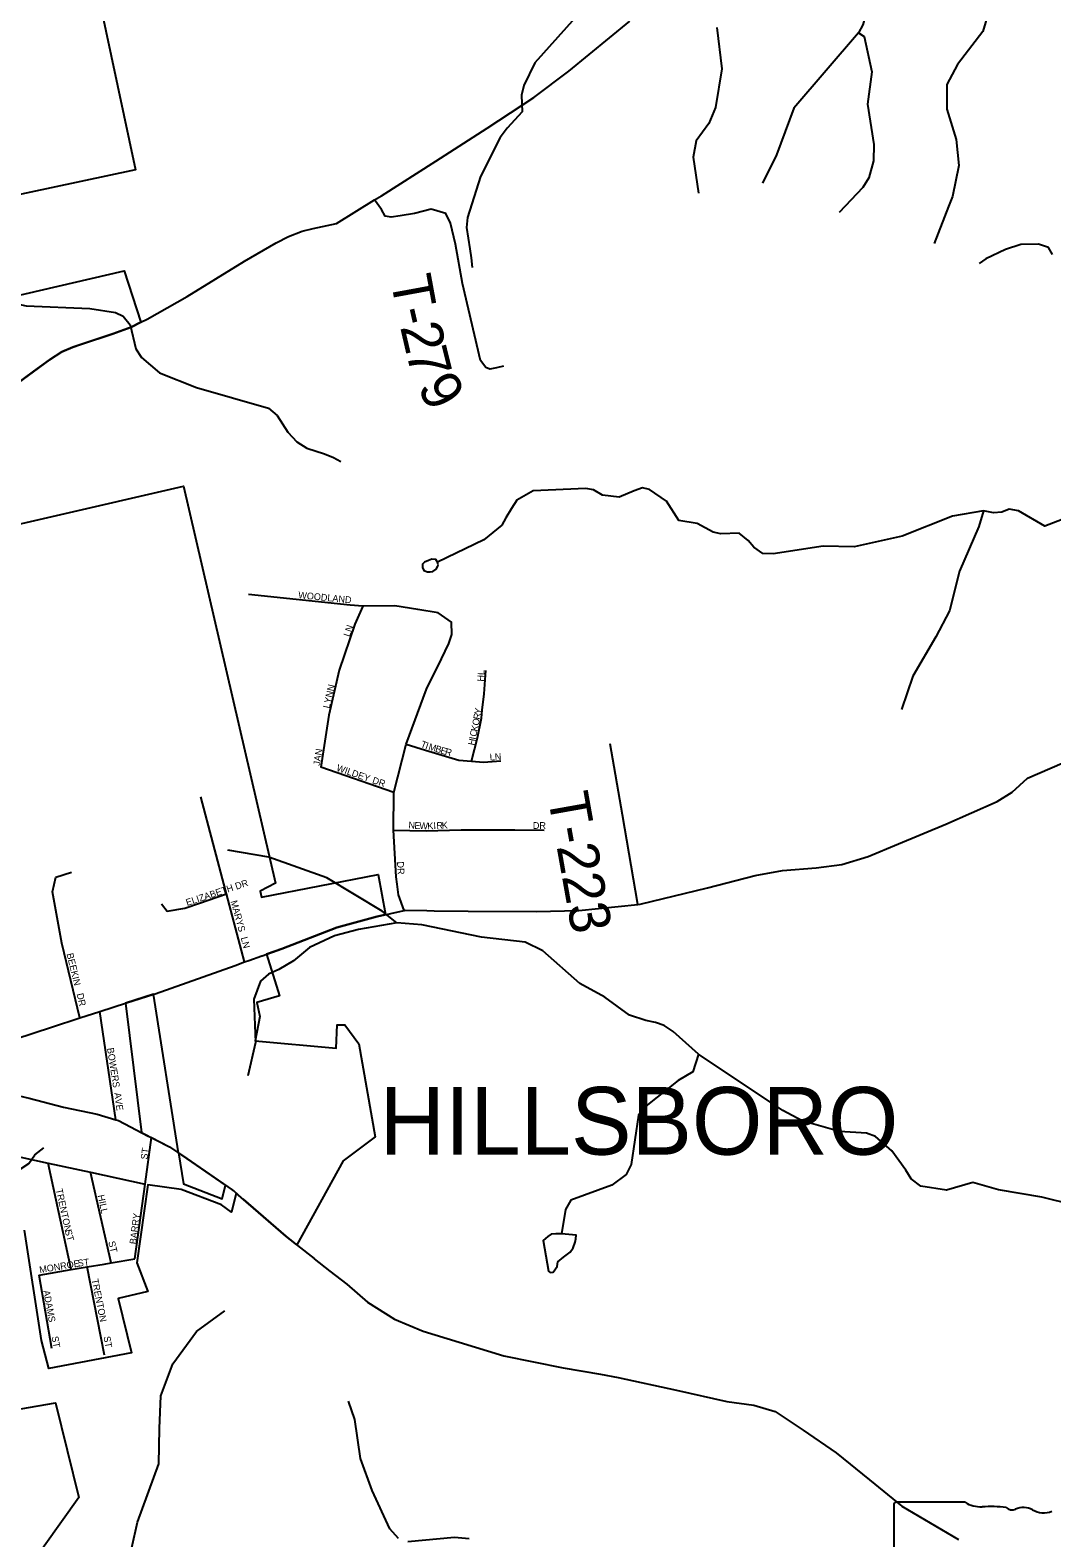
# Model space of a CAD drawing. Extents: x 1525783 to 1900577, y 218250 to 627376.
# Drawn here: x 1656538 to 1664074, y 435875 to 446999 of the extents above; entities that cross this region are included whole.
import ezdxf

# ---------------------------------------------------------------- set-up
doc = ezdxf.new("R2010")
doc.units = 0
for name, color, linetype in [('GM_X_City_Street', 7, 'Continuous'), ('GM_X_City_Street_Text', 7, 'Continuous'), ('GM_X_Corporation', 7, 'Continuous'), ('GM_X_Corporation_Text', 7, 'Continuous'), ('GM_X_Minor_Lake', 7, 'Continuous'), ('GM_X_Minor_River', 7, 'Continuous'), ('GM_X_State_Route', 7, 'Continuous'), ('GM_X_State_Shield', 7, 'Continuous'), ('GM_X_Township_Road', 7, 'Continuous'), ('GM_X_Township_Road_Text', 7, 'Continuous'), ('GM_X_Township_Subdivision', 7, 'Continuous'), ('GM_X_Township_Subdivision_Text', 7, 'Continuous'), ('GM_X_US_Route', 7, 'Continuous')]:
    doc.layers.add(name, color=color, linetype=linetype)

msp = doc.modelspace()

# ---------------------------------------------------------------- linework, layer by layer
at = {"layer": 'GM_X_City_Street'}
for points in [[(1657980, 440653), (1657980, 440653), (1657798, 441342)], [(1656905, 439711), (1656773, 440263), (1656704, 440641), (1656727, 440750), (1656842, 440787)], [(1658120, 440124), (1657987, 440627), (1657980, 440653)], [(1657508, 440554), (1657548, 440499), (1657678, 440520), (1657788, 440558), (1657788, 440558)], [(1657788, 440558), (1657987, 440627)], [(1657170, 438960), (1657051, 439758)], [(1655247, 438934), (1655840, 438817), (1656187, 438745), (1656671, 438640), (1656983, 438572), (1657386, 438484)], [(1657310, 437934), (1657386, 438484), (1657433, 438828)], [(1656840, 437855), (1656671, 438640)], [(1657136, 437904), (1656983, 438572)], [(1656604, 437814), (1656840, 437855), (1656884, 437863), (1656958, 437875), (1657085, 437895), (1657136, 437904), (1657310, 437934)], [(1657087, 437223), (1656958, 437875)], [(1656698, 437271), (1656604, 437814)]]:
    msp.add_lwpolyline(points, dxfattribs=at)
at = {"layer": 'GM_X_Corporation'}
for points in [[(1656785, 448461), (1657315, 445968), (1655515, 445585)], [(1655662, 444859), (1657231, 445224), (1657355, 444844), (1657283, 444808), (1657148, 444760), (1656853, 444660), (1656773, 444626), (1656680, 444567), (1656365, 444336)], [(1655730, 443186), (1657669, 443634), (1658347, 440706), (1658234, 440646), (1658245, 440602), (1659105, 440769), (1659159, 440474), (1659097, 440460), (1658801, 440378), (1658395, 440222), (1658282, 440182), (1658377, 439875), (1658210, 439824), (1658231, 439722), (1658199, 439541), (1658796, 439489), (1658802, 439660), (1658860, 439660), (1658963, 439519), (1659084, 438834), (1658848, 438656), (1658505, 438037), (1658424, 438102), (1658058, 438419), (1658023, 438277), (1657949, 438331), (1657652, 438445), (1657405, 438480), (1657326, 437905), (1657405, 437693), (1657187, 437642), (1657285, 437241), (1656675, 437125), (1656622, 437332), (1656496, 438146)], [(1655588, 436674), (1656726, 436872), (1656897, 436173), (1656268, 435291)]]:
    msp.add_lwpolyline(points, dxfattribs=at)
msp.add_lwpolyline([(1657241, 439819), (1657360, 438865), (1657565, 438759), (1657633, 438715), (1657669, 438487), (1657954, 438377), (1657979, 438477), (1657693, 438675), (1657633, 438715), (1657448, 439886)], close=True, dxfattribs=at)
at = {"layer": 'GM_X_Minor_Lake'}
for points in [[(1659543, 443075), (1659531, 443094), (1659501, 443096), (1659477, 443086), (1659447, 443073), (1659432, 443059), (1659432, 443035), (1659443, 443013), (1659469, 443002), (1659489, 443002), (1659509, 443006), (1659532, 443023), (1659546, 443045), (1659548, 443055)], [(1659548, 443055), (1659543, 443075)], [(1660456, 438118), (1660416, 438119), (1660382, 438116), (1660356, 438098), (1660321, 438069), (1660361, 437843), (1660373, 437833), (1660395, 437835), (1660426, 437878), (1660431, 437912), (1660473, 437946), (1660520, 437983), (1660543, 438015), (1660557, 438057), (1660564, 438082)], [(1660564, 438082), (1660565, 438108), (1660456, 438118)]]:
    msp.add_lwpolyline(points, dxfattribs=at)
at = {"layer": 'GM_X_Minor_River'}
for points in [[(1664100, 448598), (1663841, 448718), (1663657, 448717), (1663494, 448660), (1663379, 448524), (1663290, 448330), (1663239, 448275), (1663117, 448205), (1663045, 448186), (1662982, 448125), (1662940, 448052), (1662878, 447790), (1662756, 447467), (1662746, 447393), (1662716, 447169), (1662680, 447039), (1662647, 446980), (1662172, 446424), (1662044, 446079), (1661940, 445870)], [(1664504, 448468), (1664573, 448417), (1664488, 448266), (1664353, 448126), (1664306, 447938), (1664231, 447811), (1664121, 447685), (1663985, 447579), (1663732, 447448), (1663662, 447323), (1663566, 446990), (1663379, 446745), (1663299, 446599), (1663299, 446417), (1663369, 446193), (1663388, 446000), (1663340, 445772), (1663312, 445699), (1663205, 445426)], [(1661319, 447837), (1661316, 447907), (1661251, 447844), (1661081, 447524), (1661048, 447468), (1660917, 447338), (1660650, 447174), (1660599, 447137), (1660260, 446759), (1660179, 446590), (1660162, 446520), (1660167, 446396), (1660057, 446276), (1660004, 446208), (1659859, 445920), (1659763, 445617), (1659756, 445543), (1659781, 445386), (1659792, 445319), (1659798, 445249)], [(1661602, 447019), (1661639, 446714), (1661592, 446430), (1661545, 446310), (1661451, 446184), (1661429, 446062), (1661468, 445796)], [(1662647, 446980), (1662690, 446953), (1662746, 446693), (1662713, 446453), (1662762, 446155), (1662758, 446035), (1662725, 445911), (1662680, 445838), (1662505, 445654)], [(1664079, 445345), (1664048, 445397), (1663976, 445421), (1663846, 445417), (1663731, 445381), (1663588, 445311), (1663537, 445278)], [(1655107, 445225), (1655112, 445201), (1655372, 445026), (1655521, 444997), (1655977, 445080), (1656508, 444966), (1656978, 444946), (1657167, 444915), (1657225, 444888), (1657276, 444825), (1657317, 444648), (1657360, 444583), (1657492, 444472), (1657766, 444363), (1658296, 444210), (1658361, 444156), (1658439, 444033), (1658506, 443963), (1658579, 443916), (1658708, 443874), (1658776, 443846), (1658829, 443816)], [(1664151, 443390), (1664022, 443340), (1663828, 443452), (1663758, 443465), (1663706, 443444), (1663644, 443437), (1663570, 443454), (1663341, 443414), (1662970, 443266), (1662837, 443236), (1662616, 443186), (1662386, 443193), (1662018, 443136), (1661942, 443137), (1661875, 443184), (1661834, 443235), (1661767, 443288), (1661633, 443282), (1661577, 443295), (1661458, 443360), (1661322, 443382), (1661231, 443524), (1661106, 443610), (1661054, 443623), (1660992, 443600), (1660883, 443554), (1660759, 443568), (1660692, 443607), (1660636, 443618), (1660249, 443601), (1660128, 443531), (1660088, 443469), (1660047, 443400), (1660016, 443348), (1659884, 443240), (1659543, 443075)], [(1663570, 443454), (1663536, 443336), (1663392, 443008), (1663320, 442714), (1663217, 442524), (1663049, 442232), (1662965, 441986)], [(1659242, 440413), (1659134, 440499), (1658726, 440745), (1658298, 440898), (1657995, 440948)], [(1664228, 438331), (1663999, 438389), (1663680, 438443), (1663490, 438496), (1663297, 438441), (1663108, 438470), (1663036, 438524), (1662998, 438587), (1662894, 438731), (1662772, 438837), (1662708, 438860), (1662508, 438872), (1662233, 438951), (1662090, 439027), (1661467, 439443), (1661280, 439610), (1661215, 439656), (1661151, 439677), (1661079, 439692), (1660958, 439732), (1660778, 439864), (1660592, 439965), (1660320, 440206), (1660189, 440269), (1659867, 440308), (1659426, 440398), (1659242, 440413), (1658961, 440364), (1658782, 440317), (1658598, 440232), (1658480, 440133), (1658373, 440069), (1658296, 440034), (1658237, 439983), (1658187, 439849), (1658201, 439530), (1658143, 439283)], [(1661467, 439443), (1661427, 439313), (1661318, 439249), (1661078, 439060), (1661025, 438993), (1660972, 438629), (1660933, 438555), (1660829, 438477), (1660525, 438366), (1660486, 438298), (1660456, 438118)], [(1656059, 435729), (1655940, 435903), (1655888, 436155), (1655841, 436224), (1655697, 436419), (1655627, 436550), (1655592, 436731), (1655577, 437119), (1655580, 437301), (1655548, 437486), (1655416, 437835), (1655419, 437885), (1655489, 438022), (1655537, 438090), (1655642, 438174), (1655797, 438212), (1655993, 438301), (1656349, 438519), (1656529, 438638), (1656573, 438702), (1656640, 438753)], [(1657156, 434742), (1657228, 434845), (1657242, 435085), (1657336, 435410), (1657328, 435525), (1657295, 435658), (1657287, 435804), (1657329, 435990), (1657487, 436420), (1657491, 436681), (1657502, 436923), (1657590, 437158), (1657764, 437398), (1657975, 437549)], [(1659255, 435871), (1659192, 435942), (1659061, 436225), (1658975, 436461), (1658932, 436747), (1658886, 436884)], [(1659777, 435868), (1659669, 435878), (1659324, 435846)]]:
    msp.add_lwpolyline(points, dxfattribs=at)
at = {"layer": 'GM_X_State_Route'}
for points in [[(1657355, 444844), (1657355, 444844), (1657401, 444868), (1657697, 445034), (1658120, 445295), (1658352, 445430), (1658444, 445478), (1658544, 445517), (1658626, 445535), (1658798, 445573), (1659079, 445747), (1659130, 445778), (1659530, 446032), (1659908, 446276), (1660252, 446502), (1660512, 446696), (1660960, 447066)], [(1656909, 444679), (1657148, 444760), (1657283, 444808), (1657355, 444844)], [(1656114, 444163), (1656365, 444336), (1656565, 444483), (1656680, 444567), (1656773, 444626), (1656853, 444660), (1656909, 444679)], [(1655688, 439317), (1655926, 439261), (1656265, 439181), (1656532, 439118), (1656784, 439052), (1657032, 439001), (1657170, 438960), (1657190, 438954), (1657408, 438840)], [(1657408, 438840), (1657410, 438840), (1657433, 438828), (1657565, 438759), (1657693, 438675), (1657724, 438654), (1657725, 438653)], [(1657725, 438653), (1658028, 438444), (1658029, 438443)], [(1658029, 438443), (1658037, 438438), (1658108, 438375), (1658109, 438375)], [(1658109, 438375), (1658424, 438102), (1658510, 438033)], [(1658510, 438033), (1658633, 437935), (1658634, 437934)], [(1658634, 437934), (1658748, 437843), (1658874, 437747), (1659027, 437614), (1659225, 437489), (1659438, 437400), (1659702, 437318), (1660033, 437219), (1660470, 437130), (1660744, 437082)], [(1660744, 437082), (1660874, 437059), (1661305, 436964), (1661677, 436882), (1661876, 436854), (1662034, 436807), (1662239, 436670), (1662484, 436502), (1662730, 436302), (1662968, 436108), (1663385, 435862)]]:
    msp.add_lwpolyline(points, dxfattribs=at)
at = {"layer": 'GM_X_State_Shield'}
for p, q in [((1662908, 436120), (1662908, 435063)), ((1663435, 436138), (1662925, 436138))]:
    msp.add_line(p, q, dxfattribs=at)
for centre, major_axis, start_param, end_param in [((1662928, 436122), (20.2, 0), 1.712693, 3.28349), ((1663556, 436260), (196, 0), 4.042523, 4.731795), ((1663621, 435544), (702, 0), 1.404758, 1.657858), ((1663780, 436127), (56.4, 0), 3.836095, 5.185415), ((1663863, 436005), (117, 0), 0.950623, 2.079405), ((1664015, 436173), (141, 0), 4.081561, 5.145723)]:
    msp.add_ellipse(centre, major_axis=major_axis, ratio=0.8, start_param=start_param, end_param=end_param, dxfattribs=at)
at = {"layer": 'GM_X_Township_Road'}
for points in [[(1660029, 444520), (1659979, 444507), (1659928, 444498), (1659898, 444510), (1659859, 444561), (1659727, 445129), (1659676, 445421), (1659638, 445576), (1659603, 445646), (1659497, 445678), (1659374, 445646), (1659268, 445629), (1659201, 445620), (1659157, 445627), (1659130, 445675), (1659079, 445747)], [(1661019, 440548), (1660907, 441210), (1660815, 441733)]]:
    msp.add_lwpolyline(points, dxfattribs=at)
at = {"layer": 'GM_X_Township_Subdivision'}
for points in [[(1659397, 442725), (1659227, 442752), (1658992, 442749), (1658899, 442757), (1658148, 442836)], [(1658992, 442749), (1658934, 442616), (1658818, 442276), (1658741, 441944), (1658681, 441562)], [(1659572, 442362), (1659626, 442473), (1659649, 442541), (1659647, 442631), (1659547, 442701), (1659397, 442725), (1659397, 442725)], [(1659245, 440699), (1659238, 440752), (1659217, 441096), (1659221, 441374), (1659312, 441732), (1659462, 442136), (1659572, 442362)], [(1659794, 441606), (1659838, 441778), (1659867, 441923), (1659873, 441982), (1659888, 442103), (1659900, 442274)], [(1659312, 441732), (1659453, 441687), (1659701, 441613), (1659794, 441606), (1659883, 441598), (1660010, 441609)], [(1659221, 441374), (1658681, 441562)], [(1659217, 441096), (1659460, 441091), (1659717, 441099), (1659869, 441098), (1660114, 441098), (1660330, 441096)], [(1659297, 440504), (1659254, 440620), (1659245, 440699)]]:
    msp.add_lwpolyline(points, dxfattribs=at)
at = {"layer": 'GM_X_US_Route'}
for points in [[(1659517, 440502), (1659770, 440498), (1660271, 440497), (1660584, 440505), (1661019, 440548), (1661037, 440550), (1661534, 440672), (1661885, 440762), (1662088, 440798), (1662336, 440818), (1662526, 440843), (1662720, 440903), (1662942, 440995), (1663291, 441141), (1663671, 441307), (1663780, 441376), (1663894, 441481), (1664151, 441592)], [(1658248, 440170), (1658250, 440170), (1658395, 440222), (1658801, 440378), (1659097, 440460), (1659099, 440460)], [(1659099, 440460), (1659297, 440504), (1659304, 440506), (1659463, 440503), (1659517, 440502)], [(1657450, 439887), (1657460, 439890), (1658050, 440099), (1658120, 440124), (1658151, 440135), (1658248, 440170)], [(1657249, 439822), (1657450, 439887), (1657450, 439887)], [(1656695, 439643), (1656905, 439711), (1657051, 439758), (1657249, 439822), (1657249, 439822)], [(1655688, 439317), (1656433, 439558), (1656695, 439643), (1656695, 439643)]]:
    msp.add_lwpolyline(points, dxfattribs=at)

# ---------------------------------------------------------------- texts
at = {"layer": 'GM_X_City_Street_Text'}
for s, rotation, p in [('ELIZABETH DR', 18.2522, (1657696, 440537)), ('MARYS', 285.4593, (1658016, 440571)), ('LN', 285.5235, (1658091, 440302)), ('BEEKIN', 283.762, (1656806, 440183)), ('DR', 282.5327, (1656881, 439888)), ('BOWERS', 278.9735, (1657105, 439487)), ('AVE', 277.8519, (1657158, 439157)), ('ST', 82.8783, (1657403, 438664)), ('TRENTON', 282.3392, (1656727, 438445)), ('HILL', 282.3385, (1657035, 438401)), ('BARRY', 82.8744, (1657320, 438039)), ('ST', 284.931, (1656793, 438142)), ('ST', 284.033, (1657114, 438058)), ('MONROE', 9.4605, (1656610, 437828)), ('ST', 7.1351, (1656892, 437876)), ('TRENTON', 281.4803, (1656991, 437781)), ('ADAMS', 280.4086, (1656634, 437697)), ('ST', 280.6188, (1656696, 437358)), ('ST', 280.6188, (1657079, 437358))]:
    msp.add_text(s, height=50, rotation=rotation, dxfattribs=at).set_placement(p)
at = {"layer": 'GM_X_Corporation_Text'}
msp.add_text('HILLSBORO', height=500, rotation=0, dxfattribs=at).set_placement((1659115, 438702))
at = {"layer": 'GM_X_Township_Road_Text'}
for s, rotation, p in [('T', 280.4354, (1659195, 445166)), ('-', 282.844, (1659238, 444932)), ('2', 283.0823, (1659266, 444811)), ('7', 284.0112, (1659309, 444626)), ('9', 299.8666, (1659388, 444363)), ('T-223', 280.1047, (1660354, 441350))]:
    msp.add_text(s, height=300, rotation=rotation, dxfattribs=at).set_placement(p)
at = {"layer": 'GM_X_Township_Subdivision_Text'}
for s, rotation, p in [('WOODLAND', 354.4281, (1658514, 442808)), ('LN', 71.5614, (1658895, 442520)), ('HL', 86.9833, (1659885, 442192)), ('LYNN', 77.093, (1658746, 441992)), ('Y', 80.9725, (1659863, 441950)), ('K', 78.0107, (1659837, 441822)), ('O', 78.0107, (1659846, 441865)), ('R', 79.7543, (1659855, 441910)), ('T', 338.7516, (1659414, 441712)), ('H', 78.0106, (1659815, 441719)), ('I', 77.9999, (1659824, 441762)), ('C', 77.9984, (1659828, 441783)), ('JAN', 80.9095, (1658675, 441569)), ('I', 341.0524, (1659449, 441699)), ('M', 343.4263, (1659472, 441691)), ('B', 343.6868, (1659522, 441676)), ('E', 343.6868, (1659560, 441664)), ('R', 343.681, (1659594, 441655)), ('LN', 3.1781, (1659929, 441611)), ('WILDEY', 340.9087, (1658793, 441536)), ('DR', 341.5632, (1659057, 441444)), ('N', 356.2601, (1659327, 441110)), ('E', 356.2646, (1659371, 441107)), ('W', 357.4471, (1659408, 441105)), ('K', 2.4367, (1659469, 441102)), ('I', 2.9961, (1659514, 441104)), ('R', 3.0202, (1659536, 441105)), ('K', 3.0248, (1659575, 441107)), ('DR', 0, (1660246, 441106)), ('DR', 273.011, (1659244, 440864))]:
    msp.add_text(s, height=50, rotation=rotation, dxfattribs=at).set_placement(p)

doc.saveas('drawing.dxf')
